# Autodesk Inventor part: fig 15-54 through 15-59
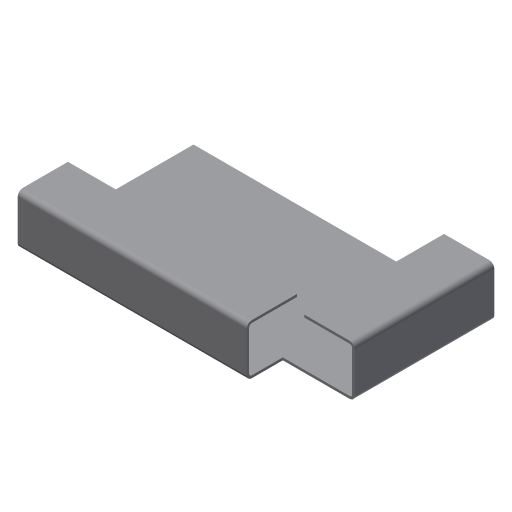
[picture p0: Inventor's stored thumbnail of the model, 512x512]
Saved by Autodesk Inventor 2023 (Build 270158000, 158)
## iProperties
Created: 2008-06
Part Number: fig 15-54 through 15-59
Material: Generic
Document SubType Name: Sheet Metal
Designer: CADCIM
Density: 1 g/cm^3
Sheet Metal Rule: Default_mm
Appearance: Default
Author: CADCIM
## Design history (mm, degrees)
node "Face1"
  sketch "Sketch1"
    geometry: L1 (-32.219, 35.011)-(27.554, 35.011); L2 (27.554, 35.011)-(27.554, 7.255); L3 (13.281, 0.063)-(-32.219, 0.063); L4 (-32.219, 0.063)-(-32.219, 35.011); L5 (13.281, 0.063)-(13.281, 7.255); L6 (13.281, 7.255)-(27.554, 7.255)
    constraints: 12 end point, 2 parallel, 2 perpendicular, 1 horizontal, 1 vertical
node "Flange5"
node "Flange6"
node "Flange7"
node "Flange8"
body "Solid1"
face "Plate1" dims "d90" = 0.5 (= Thickness)
sketch "Sketch6"
  geometry: L1 (0, 10)-(-45.501, 10); L2 (-45.501, 10)-(-45.501, 0); 1 other entity
  constraints: 4 end point, 4 other
face "Plate6" dims "d50" = 0.5 (= BendReliefWidth), "d51" = 0.25 (= BendReliefDepth), "d52" = 1 (= MinimumRemnant), "d53" = 0.5 (= BendRadius), "d54" = 10, "d55" = 90 deg, "d56" = 0.5 (= BendRadius), "d57" = 2 (= CornerReliefSize), "d58" = 0.5 (= GapSize), "d59" = 0.5 (= JacobiRadiusSize), "d90" = 0.5 (= Thickness), "SeamGap" = 0.01
bend "Bend5" dims "d50" = 0.5 (= BendReliefWidth), "d51" = 0.25 (= BendReliefDepth), "d52" = 1 (= MinimumRemnant), "d53" = 0.5 (= BendRadius), "d54" = 10, "d55" = 90 deg, "d56" = 0.5 (= BendRadius), "d90" = 0.5 (= Thickness), "SeamGap" = 0.01
feature "Corner5" dims "d54" = 10, "d55" = 90 deg, "d57" = 2 (= CornerReliefSize), "d58" = 0.5 (= GapSize), "d59" = 0.5 (= JacobiRadiusSize)
sketch "Sketch7"
  geometry: L1 (0, 10)-(-45.501, 10); L2 (-45.501, 10)-(-45.501, 0); 1 other entity
  constraints: 4 end point, 4 other
face "Plate7" dims "d60" = 0.5 (= BendReliefWidth), "d61" = 0.25 (= BendReliefDepth), "d62" = 1 (= MinimumRemnant), "d63" = 0.5 (= BendRadius), "d64" = 10, "d65" = 90 deg, "d66" = 0.5 (= BendRadius), "d67" = 2 (= CornerReliefSize), "d68" = 0.5 (= GapSize), "d69" = 0.5 (= JacobiRadiusSize), "d90" = 0.5 (= Thickness), "SeamGap" = 0.01
bend "Bend6" dims "d60" = 0.5 (= BendReliefWidth), "d61" = 0.25 (= BendReliefDepth), "d62" = 1 (= MinimumRemnant), "d63" = 0.5 (= BendRadius), "d64" = 10, "d65" = 90 deg, "d66" = 0.5 (= BendRadius), "d90" = 0.5 (= Thickness), "SeamGap" = 0.01
feature "Corner6" dims "d64" = 10, "d65" = 90 deg, "d67" = 2 (= CornerReliefSize), "d68" = 0.5 (= GapSize), "d69" = 0.5 (= JacobiRadiusSize)
sketch "Sketch8"
  geometry: L1 (0, 10)-(-27.756, 10); L2 (-27.756, 10)-(-27.756, 0); 1 other entity
  constraints: 4 end point, 4 other
face "Plate8" dims "d70" = 0.5 (= BendReliefWidth), "d71" = 0.25 (= BendReliefDepth), "d72" = 1 (= MinimumRemnant), "d73" = 0.5 (= BendRadius), "d74" = 10, "d75" = 90 deg, "d76" = 0.5 (= BendRadius), "d77" = 2 (= CornerReliefSize), "d78" = 0.5 (= GapSize), "d79" = 0.5 (= JacobiRadiusSize), "d90" = 0.5 (= Thickness), "SeamGap" = 0.01
bend "Bend7" dims "d70" = 0.5 (= BendReliefWidth), "d71" = 0.25 (= BendReliefDepth), "d72" = 1 (= MinimumRemnant), "d73" = 0.5 (= BendRadius), "d74" = 10, "d75" = 90 deg, "d76" = 0.5 (= BendRadius), "d90" = 0.5 (= Thickness), "SeamGap" = 0.01
feature "Corner7" dims "d74" = 10, "d75" = 90 deg, "d77" = 2 (= CornerReliefSize), "d78" = 0.5 (= GapSize), "d79" = 0.5 (= JacobiRadiusSize)
sketch "Sketch9"
  geometry: L1 (-10, 0)-(-10, -27.756); L2 (-10, -27.756)-(0, -27.756); 1 other entity
  constraints: 4 end point, 4 other
face "Plate9" dims "d80" = 0.5 (= BendReliefWidth), "d81" = 0.25 (= BendReliefDepth), "d82" = 1 (= MinimumRemnant), "d83" = 0.5 (= BendRadius), "d84" = 10, "d85" = 90 deg, "d86" = 0.5 (= BendRadius), "d87" = 2 (= CornerReliefSize), "d88" = 0.5 (= GapSize), "d89" = 0.5 (= JacobiRadiusSize), "d90" = 0.5 (= Thickness), "SeamGap" = 0.01
bend "Bend8" dims "d80" = 0.5 (= BendReliefWidth), "d81" = 0.25 (= BendReliefDepth), "d82" = 1 (= MinimumRemnant), "d83" = 0.5 (= BendRadius), "d84" = 10, "d85" = 90 deg, "d86" = 0.5 (= BendRadius), "d90" = 0.5 (= Thickness), "SeamGap" = 0.01
feature "Corner8" dims "d84" = 10, "d85" = 90 deg, "d87" = 2 (= CornerReliefSize), "d88" = 0.5 (= GapSize), "d89" = 0.5 (= JacobiRadiusSize)
other parameters: "Thickness" = 0.5, "BendRadius" = 0.5 (= Thickness), "BendReliefWidth" = 0.5 (= Thickness), "BendReliefDepth" = 0.25 (= 0.5 x Thickness), "CornerReliefSize" = 2 (= 4 x Thickness), "MinimumRemnant" = 1 (= 2 x Thickness), "TransitionRadius" = 0.5 (= BendRadius), "JacobiRadiusSize" = 0.5 (= BendRadius), "d0" = 0.5 (= BendRadius), "GapSize" = 0.5 (= Thickness)
